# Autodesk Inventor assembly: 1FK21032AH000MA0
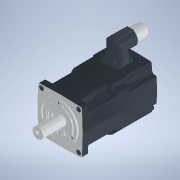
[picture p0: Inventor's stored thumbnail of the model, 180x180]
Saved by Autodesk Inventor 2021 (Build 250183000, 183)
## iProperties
Category: PARTsolutions
Created: 2026-06
Part Number: 1FK21032AH000MA0
Catalog Web Link: www.3dfindit.com
Description: 1FK21032AH000MA0-Servo synchronous motor
Document SubType Name: Assembly
Designer: psAdmin
Mass: 225.79 g
Surface Area: 767.051 cm^2
Volume: 225.79 cm^3
Density: 1 g/cm^3
Title: 1FK21032AH000MA0
Author: Cadenas PARTsolutions
Comments: Servo synchronous motor
PSOL_IDENT_0: {$CADENAS_DATA/23d-libs/siemens_ag/_cat_/45/10/1fk21032ah000ma0.prj},193 {STYP=ASS},{VTYP=3D},{NB=1F
PSOL_IDENT_1: K21032AH000MA0},{LINA=1FK21032AH000MA0},{NN=1FK21032AH000MA0},{DATE=19.08.2025 14:00:35},{GEOMDATE=3
PSOL_IDENT_2: 0.07.2025 02:02:03},{VERSION=},{LINEID=10},{WBVAR=},{WBNUMERIC=}  {NB=1FK21032AH000MA0},{LINA=1FK210
PSOL_IDENT_3: 32AH000MA0},{KT=DUMMY},{PREVIEW=../../../_pool_/14/8e/p_d211_xx_00426j.png},{DESCSHORT=SIMOTICS S-1F
PSOL_IDENT_4: K2 HD, SINAMICS S210 3AC 400V-480V, 0.59 Nm, 4500 rpm},{DESCLONG=SIMOTICS S-1FK2 HD servo motor M0=0
PSOL_IDENT_5: .64 Nm; PN = 0.28 kW at nN=4500 rpm (380-480 V); PN = 0.167 kW at nN=2500 rpm (200-240 V); degree of
PSOL_IDENT_6: protection IP64; cylindrical shaft D14 x 30 mm; absolute encoder 22-bit + 12-bit multiturn (encoder
PSOL_IDENT_7: AM22DQC); with OCC interface; plug size M17, rotatable; SIMOTICS S-1FK2 servomotorfor a wide range
PSOL_IDENT_8: of uses in industrial environments. SIMOTICS S‑1FK2 servomotors are compact synchronous motors with
PSOL_IDENT_9: a high dynamic performance that set themselves apart as a result of their high power density, degree
PSOL_IDENT_10: of protection and overload capability. The motors are available in two variants: as High Dynamic va
PSOL_IDENT_11: riant (highest dynamic performance as a result of the low intrinsic moment of inertia for applicatio
PSOL_IDENT_12: ns demanding a high dynamic performance with low moved masses) - and as Compact variant (precise and
PSOL_IDENT_13: stable closed-loop control for medium up to large moved masses as a result of a medium intrinsic mo
PSOL_IDENT_14: ment of inertia). SIMOTICSS‑1FK2 servomotors fully exploit their strengths in a system with the SINA
PSOL_IDENT_15: MICSS210 frequency converter and simple connection using the one cable connection (OCC). Advantages
PSOL_IDENT_16: include the short control and positioning times, fast and precise correction of disturbing quantitie
PSOL_IDENT_17: s as well as stable control with a high dynamic performance. The servo motors can be configured to a
PSOL_IDENT_18: ddress a wide range of requirements. For example with and without holding brake, IP64 or IP65 degree
PSOL_IDENT_19: of protection, singleturn or multiturn absolute encoders - to name just a few. Further, the servomo
PSOL_IDENT_20: tors are available in different shaft heights extending from 20 to 100. A shaft sealing ring is avai
PSOL_IDENT_21: lable to achieve an IP65 degree of protection and for subsequent mounting at the motor or as spare p
PSOL_IDENT_22: art. SIMOTICS - the optimum motor for each and every motion control application.},{INTNO=19512533500
PSOL_IDENT_23: 4},{SUPPLIERALTNO=1FK2103-2AH00-0MA0},{MANUID=1FK21032AH000MA0},{MANUNAME=Siemens},{MANUTYPEDESC=SYN
PSOL_IDENT_24: CHRONOUS MOTOR 1FK2 HD 0,64 NM},{AAU732=SIMOTICS},{AAO057=S-1FK2},{AAU734=SIMOTICS S-1FK2 HD servo m
PSOL_IDENT_25: otor M0=0.64 Nm; PN = 0.28 kW at nN=4500 rpm (380-480 V); PN = 0.167 kW at nN=2500 rpm (200-240 V);
PSOL_IDENT_26: degree of protection IP64; cylindrical shaft D14 x 30 mm; absolute encoder 22-bit + 12-bit multiturn
PSOL_IDENT_27: (encoder AM22DQC); with OCC interface; plug size M17, rotatable;},{AAW338=SYNCHRONOUS MOTOR 1FK2 HD
PSOL_IDENT_28: 0,64 NM},{AAO742=SIMOTICS},{AAO663=4034106444624},{NOCUPEROU=1},{PRICEQUANTITY=1},{QUANTITYMIN=1},{
PSOL_IDENT_29: QUANTITYINT=1},{CTN=85015100},{COO=RO},{AAO676=1FK2103-2AH00-0MA0},{AAO677=Siemens AG},{ORDERUNIT=C6
PSOL_IDENT_30: 2},{CONTENTUNIT=C62}
NB: 1FK21032AH000MA0
NN: 1FK21032AH000MA0
NT: Servo synchronous motor
NBSYN: $MANUID.
LINA: 1FK21032AH000MA0
CATALOG: SIEMENS
PREVIEW: ../../../_pool_/14/8e/p_d211_xx_00426j.png
DESCSHORT: SIMOTICS S-1FK2 HD, SINAMICS S210 3AC 400V-480V, 0.59 Nm, 4500 rpm
DESCLONG: SIMOTICS S-1FK2 HD servo motor M0=0.64 Nm; PN = 0.28 kW at nN=4500 rpm (380-480 V); PN = 0.167 kW at nN=2500 rpm (200-240 V); degree of protection IP64; cylindr
INTNO: 195125335004
SUPPLIERALTNO: 1FK2103-2AH00-0MA0
MANUID: 1FK21032AH000MA0
MANUNAME: Siemens
MANUTYPEDESC: SYNCHRONOUS MOTOR 1FK2 HD 0,64 NM
AAU732: SIMOTICS
AAO057: S-1FK2
AAU734: SIMOTICS S-1FK2 HD servo motor M0=0.64 Nm; PN = 0.28 kW at nN=4500 rpm (380-480 V); PN = 0.167 kW at nN=2500 rpm (200-240 V); degree of protection IP64; cylindr
AAW338: SYNCHRONOUS MOTOR 1FK2 HD 0,64 NM
AAO742: SIMOTICS
AAO663: 4034106444624.0
NOCUPEROU: 1
PRICEQUANTITY: 1
QUANTITYMIN: 1
QUANTITYINT: 1
CTN: 85015100
COO: RO
ARTICLENO: 1FK21032AH000MA0
BOMINFO: 1FK21032AH000MA0
CREATOR: CADENAS GmbH
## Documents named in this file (25)
- e:\temp\worker_COMMON_19\temp\tmp_8776_0_149IQ\format_0\1FK21032AH000MA0.iam
- e:\temp\worker_COMMON_19\temp\tmp_8776_0_149IQ\format_0\1FK21032AH000MA0_PART1.ipt
- e:\temp\worker_COMMON_19\temp\tmp_8776_0_149IQ\format_0\1FK21032AH000MA0_PART2.ipt
- e:\temp\worker_COMMON_19\temp\tmp_8776_0_149IQ\format_0\1FK21032AH000MA0_PART3.ipt
- e:\temp\worker_COMMON_19\temp\tmp_8776_0_149IQ\format_0\1FK21032AH000MA0_PART4.ipt
- e:\temp\worker_COMMON_19\temp\tmp_8776_0_149IQ\format_0\1FK21032AH000MA0_PART5.ipt
- e:\temp\worker_COMMON_19\temp\tmp_8776_0_149IQ\format_0\1FK21032AH000MA0_PART6.ipt
- e:\temp\worker_COMMON_19\temp\tmp_8776_0_149IQ\format_0\1FK21032AH000MA0_PART7.ipt
- e:\temp\worker_COMMON_19\temp\tmp_8776_0_149IQ\format_0\1FK21032AH000MA0_PART8.ipt
- e:\temp\worker_COMMON_19\temp\tmp_8776_0_149IQ\format_0\1FK21032AH000MA0_PART9.ipt
- e:\temp\worker_COMMON_19\temp\tmp_8776_0_149IQ\format_0\1FK21032AH000MA0_PART10.ipt
- e:\temp\worker_COMMON_19\temp\tmp_8776_0_149IQ\format_0\1FK21032AH000MA0_PART11.ipt
- e:\temp\worker_COMMON_19\temp\tmp_8776_0_149IQ\format_0\1FK21032AH000MA0_PART12.ipt
- e:\temp\worker_COMMON_19\temp\tmp_8776_0_149IQ\format_0\1FK21032AH000MA0_PART13.ipt
- e:\temp\worker_COMMON_19\temp\tmp_8776_0_149IQ\format_0\1FK21032AH000MA0_PART14.ipt
- e:\temp\worker_COMMON_19\temp\tmp_8776_0_149IQ\format_0\1FK21032AH000MA0_PART15.ipt
- e:\temp\worker_COMMON_19\temp\tmp_8776_0_149IQ\format_0\1FK21032AH000MA0_PART16.ipt
- e:\temp\worker_COMMON_19\temp\tmp_8776_0_149IQ\format_0\1FK21032AH000MA0_PART17.ipt
- e:\temp\worker_COMMON_19\temp\tmp_8776_0_149IQ\format_0\1FK21032AH000MA0_PART18.ipt
- e:\temp\worker_COMMON_19\temp\tmp_8776_0_149IQ\format_0\1FK21032AH000MA0_PART19.ipt
- e:\temp\worker_COMMON_19\temp\tmp_8776_0_149IQ\format_0\1FK21032AH000MA0_PART20.ipt
- e:\temp\worker_COMMON_19\temp\tmp_8776_0_149IQ\format_0\1FK21032AH000MA0_PART21.ipt
- e:\temp\worker_COMMON_19\temp\tmp_8776_0_149IQ\format_0\1FK21032AH000MA0_PART22.ipt
- e:\temp\worker_COMMON_19\temp\tmp_8776_0_149IQ\format_0\1FK21032AH000MA0_PART23.ipt
- e:\temp\worker_COMMON_19\temp\tmp_8776_0_149IQ\format_0\1FK21032AH000MA0_PART24.ipt
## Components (24 placed, 24 different names)
1. 1FK21032AH000MA0_PART1:1
2. 1FK21032AH000MA0_PART2:1
3. 1FK21032AH000MA0_PART3:1
4. 1FK21032AH000MA0_PART4:1
5. 1FK21032AH000MA0_PART5:1
6. 1FK21032AH000MA0_PART6:1
7. 1FK21032AH000MA0_PART7:1
8. 1FK21032AH000MA0_PART8:1
9. 1FK21032AH000MA0_PART9:1
10. 1FK21032AH000MA0_PART10:1
11. 1FK21032AH000MA0_PART11:1
12. 1FK21032AH000MA0_PART12:1
13. 1FK21032AH000MA0_PART13:1
14. 1FK21032AH000MA0_PART14:1
15. 1FK21032AH000MA0_PART15:1
16. 1FK21032AH000MA0_PART16:1
17. 1FK21032AH000MA0_PART17:1
18. 1FK21032AH000MA0_PART18:1
19. 1FK21032AH000MA0_PART19:1
20. 1FK21032AH000MA0_PART20:1
21. 1FK21032AH000MA0_PART21:1
22. 1FK21032AH000MA0_PART22:1
23. 1FK21032AH000MA0_PART23:1
24. 1FK21032AH000MA0_PART24:1
